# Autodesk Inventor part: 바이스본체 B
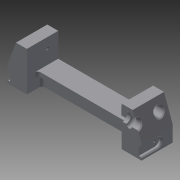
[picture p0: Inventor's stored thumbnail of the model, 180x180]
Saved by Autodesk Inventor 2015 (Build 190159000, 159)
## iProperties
Created: 2017-04
Part Number: 바이스본체 B
Material: 알루미늄 6061
Document SubType Name: Modeling
Designer: mduedu
Density: 2.71 g/cm^3
Appearance: 기본값
Mass: 246.705 g
Surface Area: 210.66 cm^2
Volume: 91.0351 cm^3
Author: mduedu
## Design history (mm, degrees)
sketch "스케치1"
  geometry: L1 (-75, 0)-(75, 0); L2 (-75, 0)-(-75, 17); L3 (-53, 17)-(53, 17); L4 (75, 17)-(75, 0); L5 (-75, 17)-(-65.173, 44); L6 (-65.173, 44)-(-53, 44); L7 (-53, 44)-(-53, 17); L8 (0, 0)-(0, 17); L9 (75, 17)-(65.173, 44); L10 (65.173, 44)-(53, 44); L11 (53, 44)-(53, 17); 1 further point
  constraints: 22 end point, 4 perpendicular, 2 horizontal alignment, 2 midpoint, 2 symmetric about line, 1 coincident, 1 collinear, 1 horizontal, 1 vertical
  dimensions: "d0" = 150 distance of L1.start L1.end; "d1" = 17 distance of L1.start L2.end; "d2" = 27 distance of L3.start L6.end; "d3" = 22 distance of L3.start L2.end; "d4" = 70 deg angle of L3 L5; "d54" = 20 deg angle of L9 L4
extrude "돌출1" new body sketch "스케치1" stored distance "d5" = 70; taper "d6" = 0 deg
sketch "스케치2"
  geometry: L1 (0, 70)-(106, 70) reference; L2 (106, 70)-(106, 0) reference; L3 (106, 0)-(0, 0) reference; L4 (0, 47)-(106, 47); L5 (106, 47)-(106, 23); L6 (106, 23)-(0, 23); L7 (0, 23)-(0, 47); L8 (0, 70)-(0, 0) reference; 2 further points
  constraints: 8 end point, 2 parallel, 2 point on line, 1 horizontal, 1 horizontal alignment, 1 midpoint, 1 perpendicular
  dimensions: "d7" = 24 distance between parallel lines of L6 L4
extrude "돌출2" cut sketch "스케치2" stored distance "d9" = 70; taper "d10" = 0 deg
sketch "스케치3"
  geometry: L1 (22, -23)-(128, -23) reference; L2 (128, -47)-(22, -47) reference; L3 (22, -18)-(128, -18); L4 (128, -52)-(22, -52); L5 (22, -18)-(22, -52); L6 (128, -18)-(128, -52); 1 further point
  constraints: 8 end point, 3 parallel, 2 point on line, 1 perpendicular
  dimensions: "d11" = 5 distance between parallel lines of L3 L1; "d12" = 5 distance between parallel lines of L4 L2
extrude "돌출3" cut sketch "스케치3" distance "d13" = 12; taper "d14" = 0 deg
fillet "모깎기1" dims "d15" = 3, "d16" = 3
sketch "스케치4"
  geometry: L1 (103, 23)-(3, 23) reference; L2 (0, 26)-(0, 0) reference; L3 (106, 0)-(0, 0) reference; L4 (106, 26)-(106, 0) reference; L5 (96, 0)-(90, 0); L6 (90, 0)-(90, 19.5); L7 (96, 19.5)-(96, 0); L8 (90, 19.5)-(96, 19.5); A1 r 3 centre (3, 26) between (0, 26) and (3, 23) reference; A2 r 3 centre (103, 26) between (103, 23) and (106, 26) reference; 1 further point
  constraints: 8 end point, 2 perpendicular, 1 horizontal, 1 parallel, 1 point on line
  dimensions: "d17" = 10 distance between parallel lines of L7 L4; "d18" = 6 distance between parallel lines of L7 L6; "d27" = 3.5 distance between parallel lines of L8 L1
extrude "돌출4" join sketch "스케치4" distance "d19" = 12; taper "d20" = 0 deg
chamfer "모따기1" distance "d21" = 3; stored, may be unused: second distance "d22" = 2, angle "d23" = 45 deg
chamfer "모따기2" distance "d24" = 3; stored, may be unused: second distance "d25" = 2, angle "d26" = 45 deg
sketch "스케치5"
  geometry: L1 (-15.5, 35.8)-(-15.5, -25.8) reference; L2 (19.5, 0)-(0, 0) reference; C1 r 6.5 at (9.5, 15); 1 further point
  constraints: 1 centre point
  dimensions: "d28" = 13 diameter of C1; "d30" = 15 distance from line of C1.centre L2; "d31" = 25 distance from line of C1.centre L1
extrude "돌출5" cut sketch "스케치5" stored distance "d32" = 12; taper "d33" = 0 deg
sketch "스케치6"
  geometry: C1 r 5 at (-10, 15); C2 r 5 at (-60, 15); A1 r 6.5 centre (-10, 15) between (-15.766, 12) and (-4.234, 12) reference; A2 r 6.5 centre (-60, 15) between (-65.766, 12) and (-54.234, 12) reference; 1 further point
  constraints: 2 centre point, 2 coincident
  dimensions: "d34" = 10 diameter of C1; "d35" = 10 diameter of C2 (= d34)
extrude "돌출6" cut sketch "스케치6" stored distance "d36" = 12; taper "d37" = 0 deg
chamfer "모따기3" distance "d38" = 1; stored, may be unused: second distance "d39" = 2, angle "d40" = 45 deg
chamfer "모따기4" distance "d41" = 1; stored, may be unused: second distance "d42" = 2, angle "d43" = 45 deg
sketch "스케치7"
  geometry: L1 (-35, 35.8)-(-35, -25.8) reference; L2 (-70, 0)-(0, 0) reference; C1 r 5 at (-35, 15); 1 further point
  constraints: 1 centre point, 1 point on line
  dimensions: "d44" = 10 diameter of C1; "d45" = 15 distance from line of C1.centre L2
extrude "돌출7" cut sketch "스케치7" stored distance "d46" = 12; taper "d47" = 0 deg
chamfer "모따기5" distance "d48" = 1; stored, may be unused: second distance "d49" = 2, angle "d50" = 45 deg
node "작업축1"
sketch "스케치8"
  geometry: L1 (-105, 32)-(105, 32) reference; L2 (58, 32)-(64, 32); L3 (64, 32)-(64, 40); L4 (64, 40)-(58, 40); L5 (58, 40)-(58, 32); L6 (53, 38)-(53, 26) reference; 1 further point
  constraints: 8 end point, 2 parallel, 1 horizontal, 1 perpendicular, 1 point on line
  dimensions: "d51" = 5 distance from line of L6 L2.start; "d52" = 6 distance of L3.end L4.end; "d53" = 16 diameter of L4 L1
revolve "회전1" sketch "스케치8" stored, may be unused: angle "d55" = 90 deg
fillet "모깎기2"
chamfer "모따기6" distance "d56" = 1; stored, may be unused: second distance "d57" = 2, angle "d58" = 45 deg
sketch "스케치9"
  geometry: L1 (17.5, 3)-(52.5, 3); L2 (52.5, 13)-(17.5, 13); L3 (70, 0)-(0, 0) reference; L4 (17.5, 8)-(52.5, 8); A1 r 5 centre (17.5, 8) between (17.5, 13) and (17.5, 3); A2 r 5 centre (52.5, 8) between (52.5, 3) and (52.5, 13); 3 further points
  constraints: 6 end point, 4 point on circle, 3 tangent, 2 centre point, 2 midpoint, 2 parallel, 1 horizontal, 1 vertical alignment
  dimensions: "d59" = 35 distance of L4.start L4.end; "d61" = 5 radius of A2; "d62" = 8 distance between parallel lines of L3 L4
extrude "돌출8" cut sketch "스케치9" distance "d63" = 3; taper "d64" = 0 deg
chamfer "모따기7" distance "d65" = 1; stored, may be unused: second distance "d66" = 2, angle "d67" = 45 deg
chamfer "모따기8" distance "d68" = 1; stored, may be unused: second distance "d69" = 2, angle "d70" = 45 deg
feature "분할1"
sketch "스케치10"
  geometry: A1 r 5 centre (0, 0) between (0, 5) and (0, -5) reference; 1 further point
  constraints: 1 coincident
hole "구멍1" sketch "스케치10" at (0, 0) diameter "d71" = 2.459; stored, may be unused: countersink angle "d75" = 90 deg, drill point angle "d77" = 120 deg; dims "d72" = 4.5, "d73" = 4, "d74" = 2, "d76" = 6
sketch "스케치11"
  geometry: L1 (0, 0)-(0, 27) reference; L2 (0, 27)-(-35, 27) reference; 2 further points
  dimensions: "d78" = 12 distance from line of point (-12, 15.5) L1; "d79" = 11.5 distance from line of point (-12, 15.5) L2
hole "구멍2" sketch "스케치11" at (-12, 15.5) diameter "d80" = 3.242; stored, may be unused: countersink angle "d84" = 90 deg, drill point angle "d86" = 120 deg; dims "d81" = 6, "d82" = 4, "d83" = 2, "d85" = 8
node "솔리드1"
mirror "대칭1"
mirror "대칭2"
mirror "대칭3"
mirror "대칭4"
node "투영된 루프1"
